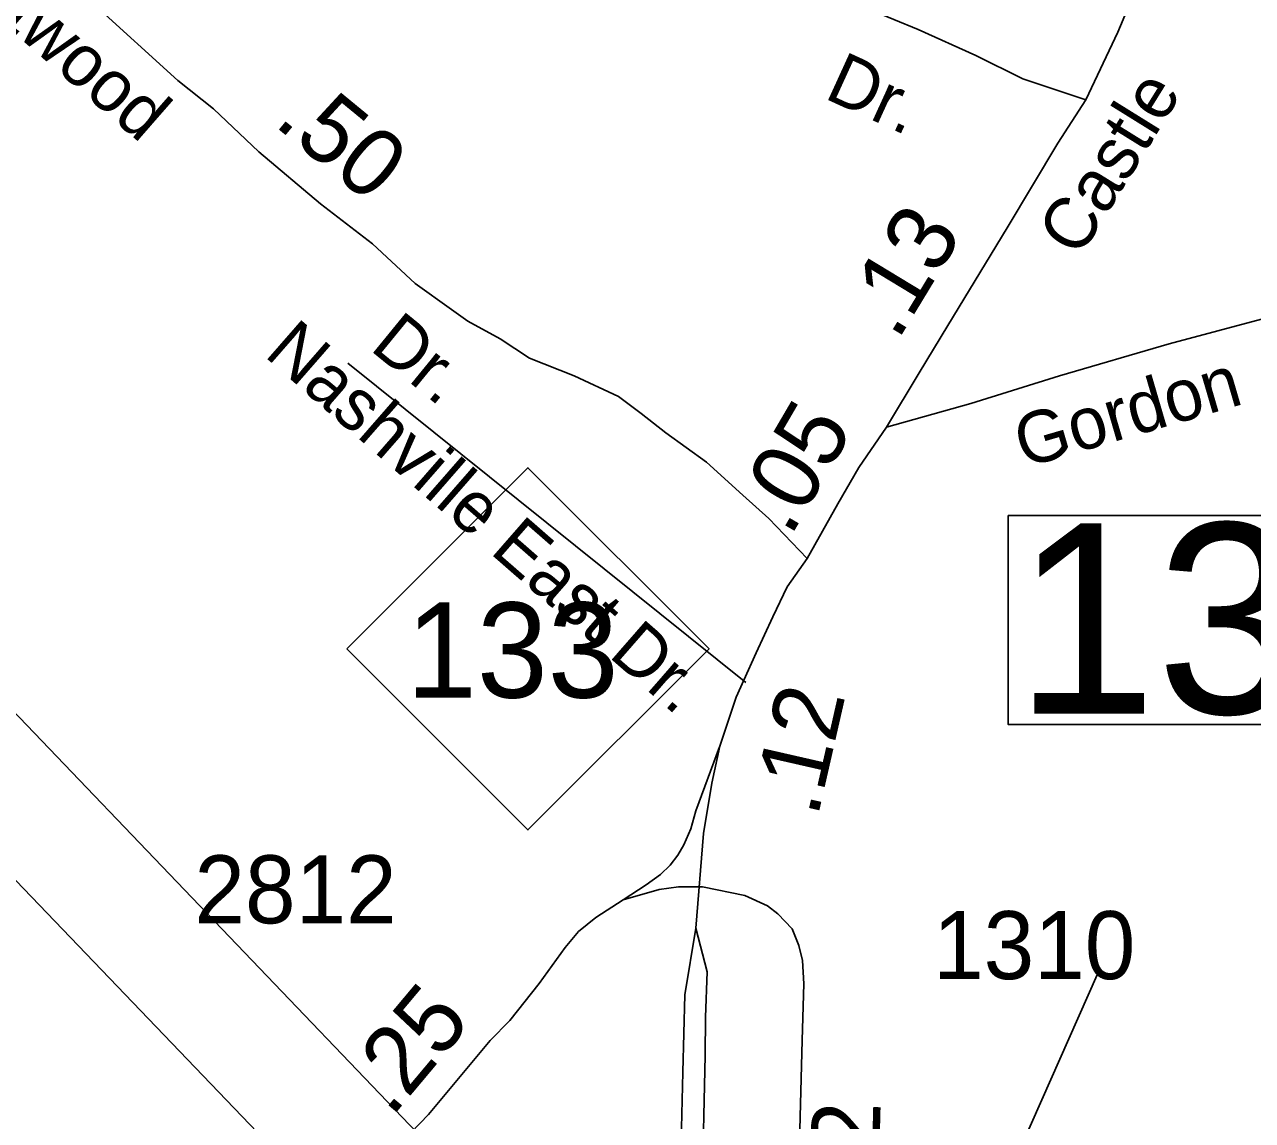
# Model space of a CAD drawing. Extents: x 2290055 to 2389491, y 66597 to 237875.
# Drawn here: x 2321946 to 2324203, y 188959 to 190974 of the extents above; entities that cross this region are included whole.
import ezdxf

# ---------------------------------------------------------------- set-up
doc = ezdxf.new("R2010")
doc.units = 0
for name, color, linetype in [('Exist Road Non-System Type 51', 7, 'Continuous'), ('Exist Road Non-System Type 51 Label', 7, 'Continuous'), ('Exist Road Primary Interstate Ramp 1 Lane Attributed', 7, 'Continuous'), ('Exist Road Primary NC Divided Attributed', 7, 'Continuous'), ('Exist Road Primary NC Label', 7, 'Continuous'), ('Exist Road Primary NC Service Mileage Hundredths English Label', 7, 'Continuous'), ('Exist Road Primary NC Shield CELL', 7, 'Continuous'), ('Exist Road Primary NC Shield Number Label', 7, 'Continuous'), ('Exist Road Primary NC UnDivided 4 Lane Attributed', 7, 'Continuous'), ('Exist Road Primary US Structure Standard Bridge Number Label', 7, 'Continuous'), ('Exist Road Secondary Mileage Hundredths English Label', 7, 'Continuous'), ('Exist Road Secondary Type 51 Attributed', 7, 'Continuous'), ('Exist Road Secondary Type 51 Label', 7, 'Continuous'), ('Exist Road Secondary Type 51 Number Label', 7, 'Continuous'), ('Exist Utilities Electrical Transmission Line', 7, 'Continuous')]:
    doc.layers.add(name, color=color, linetype=linetype)

msp = doc.modelspace()

# ---------------------------------------------------------------- linework, layer by layer
at = {"layer": 'Exist Road Non-System Type 51'}
for points in [[(2322540.5, 190351.3), (2323272.2, 189764.6)], [(2323917.8, 189227), (2323591.4, 188488.9)]]:
    msp.add_lwpolyline(points, dxfattribs=at)
at = {"layer": 'Exist Road Primary Interstate Ramp 1 Lane Attributed'}
msp.add_lwpolyline([(2323223.7, 189646.1), (2323180.5, 189528.6), (2323171.1, 189495.6), (2323158.2, 189466.1), (2323147.4, 189446.7), (2323133.1, 189428.7), (2323115.1, 189411.5), (2323089.3, 189392.1), (2323046.9, 189364.6)], dxfattribs=at)
at = {"layer": 'Exist Road Primary NC Divided Attributed'}
for points in [[(2323180.1, 189312.4), (2323159.8, 189190.1), (2323156.5, 189047.9), (2323152.7, 188893.5)], [(2323180.1, 189312.4), (2323201, 189232.7), (2323198.1, 189148.9), (2323197.2, 189078.5), (2323191.9, 188829.9), (2323184.7, 188740.4), (2323174.7, 188400.3), (2323172.7, 188279.6), (2323166.5, 187978.8), (2323157.6, 187653.4)]]:
    msp.add_lwpolyline(points, dxfattribs=at)
at = {"layer": 'Exist Road Primary NC Shield CELL'}
msp.add_lwpolyline([(2322538.6, 189826.2), (2322871.6, 190159.2), (2323204.6, 189826.2), (2322871.6, 189493.2)], close=True, dxfattribs=at)
at = {"layer": 'Exist Road Primary NC UnDivided 4 Lane Attributed'}
for points in [[(2323897.4, 190835.8), (2323956.2, 190960), (2323986.7, 191033.8), (2324009.4, 191095.4), (2324057.7, 191231.7), (2324091.7, 191342.5), (2324131.6, 191461.1), (2324159.1, 191554.4), (2324188.2, 191645.6)], [(2323530.6, 190233.9), (2323591.1, 190333.7), (2323643.6, 190420.6), (2323752.6, 190600.4), (2323845.8, 190756.2), (2323897.4, 190835.8)], [(2323384.9, 189992.1), (2323441.1, 190093.1), (2323480.1, 190159.9), (2323530.6, 190233.9)], [(2323384.9, 189992.1), (2323348, 189940.4), (2323322.1, 189885.2), (2323291.1, 189818.7), (2323268.3, 189768.7)], [(2323268.3, 189768.7), (2323254.2, 189737.4), (2323224.2, 189647.3), (2323210, 189579.6), (2323194.1, 189486.9), (2323180.1, 189312.4)]]:
    msp.add_lwpolyline(points, dxfattribs=at)
at = {"layer": 'Exist Road Primary US Structure Standard Bridge Number Label'}
msp.add_line((2323907.7, 187642.3), (2320699.2, 190991.9), dxfattribs=at)
msp.add_lwpolyline([(2323754.3, 190071.6), (2324683.3, 190071.6), (2324683.3, 189687.4), (2323754.3, 189687.4)], close=True, dxfattribs=at)
at = {"layer": 'Exist Road Secondary Type 51 Attributed'}
for points in [[(2321824.1, 191768.3), (2321905.9, 191730.9), (2322024, 191679.6), (2322083.6, 191647.3), (2322219.6, 191594.8), (2322355.6, 191520.8), (2322439.1, 191480.2), (2322538.1, 191447.2), (2322635.9, 191397.5), (2322718.2, 191360), (2322819.6, 191313.5), (2322925.8, 191255), (2323024.8, 191215.6), (2323108.3, 191179.8), (2323267, 191109.4), (2323395.8, 191055.7), (2323499.6, 191002), (2323589.1, 190965), (2323695.2, 190917.2), (2323781.1, 190874.2), (2323897.4, 190835.8)], [(2323384.9, 189992.1), (2323314.7, 190065.8), (2323267, 190108.8), (2323200.2, 190169.7), (2323125, 190223.4), (2323079.7, 190259.2), (2323037.9, 190290.2), (2322956.8, 190328.4), (2322874.5, 190360.6), (2322820.8, 190396.5), (2322761.2, 190428.7), (2322731.4, 190450.2), (2322664.6, 190497.9), (2322585.8, 190570.7), (2322490.4, 190644.7), (2322377.1, 190740.2), (2322293.6, 190819), (2322228, 190871.5), (2322074.1, 191011.2)], [(2323530.6, 190233.9), (2323685.7, 190277.1), (2323849.1, 190328.4), (2324050.7, 190386.9), (2324229.6, 190434.6), (2324450.3, 190501.5), (2324650.7, 190554), (2324778.4, 190587.4), (2324888.1, 190614.4), (2324932.2, 190620.4), (2324963.3, 190623.9), (2325006.2, 190627.5), (2325058.7, 190625.1), (2325099.2, 190631.1), (2325123.1, 190641.9), (2325152.9, 190651.1), (2325205.4, 190674.1), (2325306, 190726.7)], [(2322256.7, 188502.7), (2322396, 188659.1), (2322443.1, 188711.3), (2322518.1, 188787.6), (2322525.6, 188795.2), (2322606.9, 188884.7), (2322688.6, 188970.1), (2322753.3, 189047.3), (2322802.2, 189106.1), (2322838.2, 189142.9), (2322892.6, 189211.2), (2322939.9, 189277.4), (2322964.9, 189306.4), (2322996.5, 189332.6), (2323046.9, 189364.6), (2323113.1, 189383.6), (2323148.7, 189388.6), (2323192.4, 189388.9)], [(2323192.4, 189388.9), (2323270.5, 189372.8), (2323312, 189354), (2323331, 189339.1), (2323357.2, 189311.5), (2323369.9, 189281), (2323376.4, 189253.4), (2323378.6, 189210.5), (2323375.7, 189106.6), (2323365.5, 188706.9), (2323367.3, 188634.9), (2323378.2, 188589.9), (2323399.3, 188552.8), (2323427.6, 188521.6), (2323451.2, 188504.8), (2323474.1, 188493.2), (2323505, 188486.7), (2323530.4, 188486.7), (2323562.7, 188488.9), (2323588.5, 188488.9)]]:
    msp.add_lwpolyline(points, dxfattribs=at)
at = {"layer": 'Exist Utilities Electrical Transmission Line'}
msp.add_lwpolyline([(2322518.1, 188787.6), (2320726, 190655.5), (2321161.7, 192135.8), (2321162.4, 192138.3)], dxfattribs=at)

# ---------------------------------------------------------------- texts
at = {"layer": 'Exist Road Non-System Type 51 Label'}
msp.add_text('Nashville East Dr.', height=95, rotation=318.886, dxfattribs=at).set_placement((2322384.8, 190365.7))
at = {"layer": 'Exist Road Primary NC Label'}
msp.add_text('Castle', height=95, rotation=58.1533, dxfattribs=at).set_placement((2323885, 190543.2))
at = {"layer": 'Exist Road Primary NC Service Mileage Hundredths English Label'}
for s, rotation, p in [('.13', 58.7893, (2323551.1, 190390.9)), ('.05', 59.7306, (2323353.8, 190030.2)), ('.12', 77.1487, (2323404, 189514.5))]:
    msp.add_text(s, height=125, rotation=rotation, dxfattribs=at).set_placement(p)
at = {"layer": 'Exist Road Primary NC Shield Number Label'}
msp.add_text('133', height=175, dxfattribs=at).set_placement((2322647.8, 189736.5))
at = {"layer": 'Exist Road Primary US Structure Standard Bridge Number Label'}
msp.add_text('133', height=350, dxfattribs=at).set_placement((2323766.8, 189707.2))
at = {"layer": 'Exist Road Secondary Mileage Hundredths English Label'}
for s, rotation, p in [('.50', 320.5495, (2322402.1, 190790.6)), ('.25', 50.0034, (2322620.3, 188962.8)), ('.22', 88.5426, (2323514.2, 188759.6))]:
    msp.add_text(s, height=125, rotation=rotation, dxfattribs=at).set_placement(p)
at = {"layer": 'Exist Road Secondary Type 51 Label'}
for s, rotation, p in [('Brentwood', 318.8491, (2321703, 191154)), ('Dr.', 335.4505, (2323414, 190839.6)), ('Dr.', 320.7519, (2322579, 190377.2)), ('Gordon', 16.2936, (2323783, 190158.3))]:
    msp.add_text(s, height=95, rotation=rotation, dxfattribs=at).set_placement(p)
at = {"layer": 'Exist Road Secondary Type 51 Number Label'}
for s, p in [('2812', (2322258.6, 189321.6)), ('1310', (2323616.4, 189219))]:
    msp.add_text(s, height=125, dxfattribs=at).set_placement(p)

doc.saveas('drawing.dxf')
